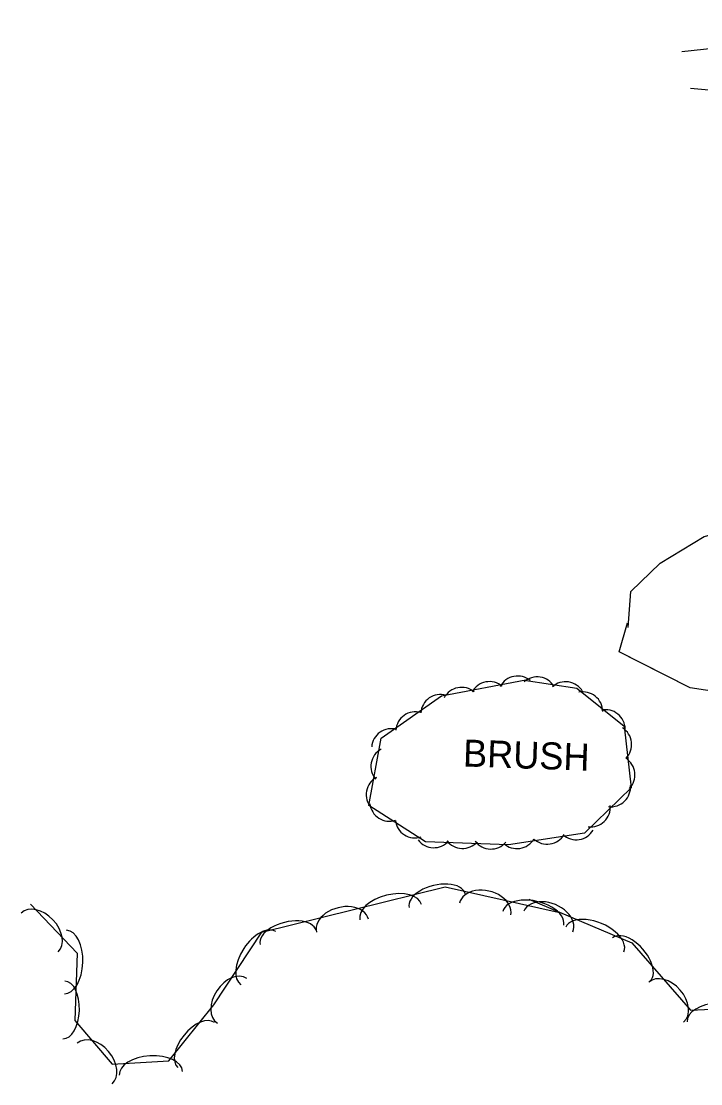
# Model space of a CAD drawing. Extents: x 978516 to 993312, y 1836504 to 1846212.
# Drawn here: x 991086.9 to 991212.7, y 1839722.3 to 1839918.8 of the extents above; entities that cross this region are included whole.
import ezdxf

# ---------------------------------------------------------------- set-up
doc = ezdxf.new("R2010")
doc.units = 0
for name, color, linetype in [('S_DRIVEWAY', 7, 'Continuous'), ('S_TREE', 7, 'Continuous'), ('S_TREE_ANNOT', 7, 'Continuous')]:
    doc.layers.add(name, color=color, linetype=linetype)

msp = doc.modelspace()

# ---------------------------------------------------------------- linework, layer by layer
at = {"layer": 'S_DRIVEWAY'}
for points in [[(991234.15, 1839918.84), (991226.33, 1839915.03), (991209.16, 1839913.19)], [(991210.79, 1839906.46), (991226.5, 1839905.03), (991234.43, 1839903.62)]]:
    msp.add_lwpolyline(points, dxfattribs=at)
at = {"layer": 'S_TREE'}
for points in [[(991199.28, 1839806.69), (991199.74, 1839813.36), (991205.17, 1839818.63), (991213.33, 1839823.55), (991225.73, 1839826.47), (991230.67, 1839822.57), (991235.2, 1839813.87), (991235.33, 1839803.4), (991231.6, 1839795.6), (991223.3, 1839793.65), (991210.73, 1839795.54), (991197.62, 1839802.19), (991199.14, 1839807.59)], [(991199.28, 1839806.69), (991199.74, 1839813.36), (991205.17, 1839818.63), (991213.33, 1839823.55), (991214.51, 1839823.83)], [(991200.96, 1839800.49), (991197.62, 1839802.19), (991199.14, 1839807.59)], [(991224.6, 1839793.95), (991223.3, 1839793.65), (991210.73, 1839795.54), (991200.96, 1839800.49)], [(991180.03, 1839796.98), (991189.75, 1839795.48), (991198.52, 1839788.45), (991199.83, 1839777.03), (991191.18, 1839768.65), (991177.13, 1839766.51), (991161.77, 1839767.03), (991151.29, 1839773.77), (991153.53, 1839786.24), (991164.71, 1839794.06), (991180.3, 1839797.05)], [(991088.66, 1839755.53), (991097.29, 1839746.44), (991096.87, 1839733.99), (991103.75, 1839725.96), (991114.22, 1839726.57), (991122.6, 1839736.88), (991131.43, 1839750.32), (991165.42, 1839758.73), (991186.29, 1839754.03)], [(991180.88, 1839756.42), (991199.93, 1839748.4), (991210.78, 1839735.9), (991230.1, 1839736.82)]]:
    msp.add_lwpolyline(points, dxfattribs=at)
for centre, start, end in [((991173.58, 1839793.05), 50.0499, 151.6468), ((991178.79, 1839794.09), 50.0499, 151.6468), ((991182.42, 1839793.92), 30.4086, 132.0055), ((991187.68, 1839793.03), 30.4086, 132.0055), ((991168.41, 1839791.99), 50.0499, 151.6468), ((991190.9, 1839791.15), 0.4908, 102.0877), ((991164.52, 1839790.68), 74.194, 175.7909), ((991159.88, 1839787.47), 74.194, 175.7909), ((991195.06, 1839787.86), 0.4908, 102.0877), ((991155.42, 1839784.35), 74.194, 175.7909), ((991196.26, 1839785.06), 315.71, 57.3069), ((991155.29, 1839781.01), 119.0456, 220.6425), ((991196.87, 1839779.44), 315.71, 57.3069), ((991154.43, 1839775.79), 119.0456, 220.6425), ((991196.06, 1839777.18), 263.2811, 4.878), ((991155.08, 1839774.5), 186.436, 288.0329), ((991192.31, 1839773.46), 263.2811, 4.878), ((991159.81, 1839771.42), 186.436, 288.0329), ((991189.65, 1839771.07), 227.8603, 329.4572), ((991163.28, 1839769.61), 217.2716, 318.8685), ((991168.58, 1839769.46), 217.2716, 318.8685), ((991178.68, 1839769.44), 227.8603, 329.4572), ((991184.27, 1839770.26), 227.8603, 329.4572), ((991173.86, 1839769.36), 217.2716, 318.8685)]:
    msp.add_arc(centre, 3.64, start, end, dxfattribs=at)
for centre, major_axis, ratio, start_param, end_param in [((991163.9, 1839756.17), (-5.18, -1.28), 0.541236, 3.14214, 6.283733), ((991155.3, 1839754.04), (-5.69, -1.41), 0.550626, 3.142158, 6.28375), ((991172.78, 1839754.63), (-4.74, 1.11), 0.697231, 3.152673, 6.294266), ((991181.7, 1839752.89), (-5.62, 1.29), 0.559666, 3.148247, 6.28984), ((991184.49, 1839752.31), (-4.55, 1.9), 0.688562, 3.138258, 6.279851), ((991090.34, 1839750.3), (-3.41, 3.59), 0.683904, 3.141593, 6.283185), ((991146.38, 1839751.57), (-4.81, -1.19), 0.685991, 3.142519, 6.284112), ((991136.33, 1839749.35), (-5.18, -1.28), 0.541236, 3.14214, 6.283733), ((991193.09, 1839748.98), (-5.38, 2.26), 0.552691, 3.139566, 6.281159), ((991095.12, 1839744.83), (0.2, 5.87), 0.54914, 3.141593, 6.283185), ((991130.81, 1839745.53), (-3.22, -4.91), 0.549778, 3.141593, 6.283185), ((991199.82, 1839745.29), (-3.47, 3.99), 0.546525, 3.141052, 6.282645), ((991125.95, 1839737.65), (-2.72, -4.14), 0.684935, 3.141593, 6.283185), ((991206.31, 1839737.42), (-3.22, 3.7), 0.692694, 3.14067, 6.282262), ((991094.82, 1839735.97), (0.18, 5.34), 0.539775, 3.141593, 6.283185), ((991216.01, 1839734.03), (-5.86, -0.28), 0.549755, 3.140915, 6.282507), ((991119.31, 1839729.47), (-3.37, -4.15), 0.540501, 3.141593, 6.283185), ((991100.53, 1839726.07), (-3.23, 3.76), 0.683865, 3.141593, 6.283185), ((991110.94, 1839724.26), (-5.86, -0.34), 0.549881, 3.141593, 6.283185)]:
    msp.add_ellipse(centre, major_axis=major_axis, ratio=ratio, start_param=start_param, end_param=end_param, dxfattribs=at)

# ---------------------------------------------------------------- texts
at = {"layer": 'S_TREE_ANNOT'}
msp.add_text('BRUSH', height=5, rotation=358.0701, dxfattribs=at).set_placement((991168.64, 1839781))

doc.saveas('drawing.dxf')
